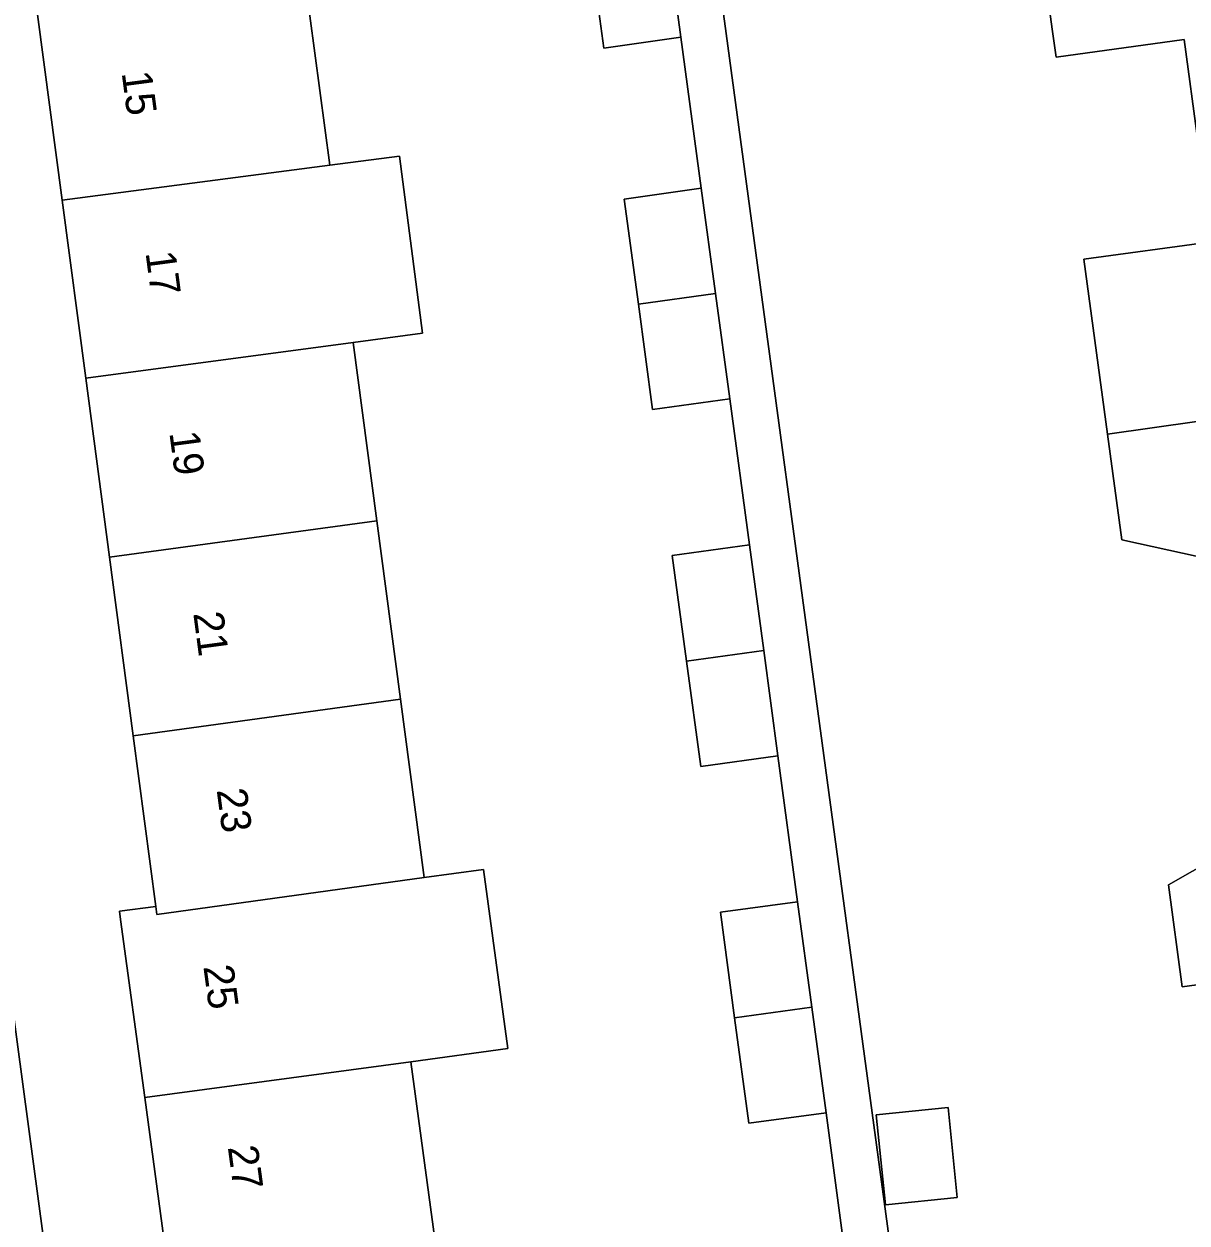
# Model space of a CAD drawing. Extents: x 163426 to 164192, y 380329 to 381641.
# Drawn here: x 163562.11 to 163600.88, y 381402.87 to 381442.84 of the extents above; entities that cross this region are included whole.
import ezdxf

# ---------------------------------------------------------------- set-up
doc = ezdxf.new("R2010")
doc.units = 0
for name, color, linetype in [('IMGEO_Erf', 7, 'Continuous'), ('IMGEO_Pand', 7, 'Continuous'), ('IMGEO_Pand_nummerreeks', 7, 'Continuous'), ('IMGEO_Voetpad_open', 7, 'Continuous')]:
    doc.layers.add(name, color=color, linetype=linetype)

msp = doc.modelspace()

# ---------------------------------------------------------------- linework, layer by layer
at = {"layer": 'IMGEO_Erf'}
for points in [[(163601.242, 381438.946), (163600.786, 381442.315), (163596.517, 381441.737), (163596.391, 381442.666), (163595.72, 381447.62)], [(163589.501, 381401.702), (163588.848, 381406.545), (163586.273, 381406.198), (163585.799, 381409.71), (163585.325, 381413.226), (163587.899, 381413.578), (163587.243, 381418.441), (163584.669, 381418.086), (163584.195, 381421.6), (163583.72, 381425.123), (163586.294, 381425.473), (163585.637, 381430.346), (163583.064, 381429.983), (163582.59, 381433.497), (163582.117, 381437.001), (163584.689, 381437.369), (163584.011, 381442.4), (163581.439, 381442.03), (163580.811, 381446.687)], [(163585.004, 381446.309), (163592.085, 381393.976)], [(163571.471, 381444.365), (163572.3, 381438.127), (163574.624, 381438.431), (163575.395, 381432.527), (163573.084, 381432.225), (163573.875, 381426.278), (163574.664, 381420.334), (163575.455, 381414.385), (163577.43, 381414.653), (163578.239, 381408.682), (163575.006, 381408.241), (163575.808, 381402.329)], [(163557.232, 381443.507), (163566.206, 381376.628), (163570.178, 381377.161), (163569.35, 381383.284), (163568.544, 381389.24), (163567.74, 381395.178), (163566.936, 381401.125), (163566.134, 381407.052), (163565.331, 381412.988), (163565.293, 381413.269), (163566.504, 381413.42), (163565.75, 381419.111), (163564.961, 381425.061), (163564.17, 381431.032), (163563.384, 381436.962), (163562.564, 381443.153)], [(163601.284, 381425.078), (163598.705, 381425.644), (163598.229, 381429.159), (163597.438, 381435.003), (163601.697, 381435.579)], [(163603.179, 381411.077), (163600.723, 381410.745), (163600.263, 381414.138), (163602.585, 381415.466)]]:
    msp.add_lwpolyline(points, dxfattribs=at)
msp.add_lwpolyline([(163590.524, 381406.471), (163592.916, 381406.715), (163593.222, 381403.715), (163590.83, 381403.471)], close=True, dxfattribs=at)
at = {"layer": 'IMGEO_Pand'}
for points in [[(163601.242, 381438.946), (163609.79, 381440.096), (163609.708, 381440.698), (163610.578, 381440.816), (163610.14, 381444.028), (163609.27, 381443.909), (163608.94, 381446.33), (163606.347, 381445.989), (163602.09, 381445.43), (163601.69, 381448.44), (163595.72, 381447.62), (163596.391, 381442.666), (163596.517, 381441.737), (163600.786, 381442.315)], [(163581.439, 381442.03), (163584.011, 381442.4), (163583.384, 381447.045), (163580.811, 381446.687)], [(163563.384, 381436.962), (163572.3, 381438.127), (163571.471, 381444.365), (163567.519, 381443.827), (163562.564, 381443.153)], [(163604.182, 381430.011), (163603.784, 381432.938), (163608.262, 381433.547), (163610.64, 381433.87), (163610.31, 381436.291), (163611.179, 381436.409), (163610.742, 381439.611), (163609.873, 381439.492), (163609.79, 381440.096), (163601.242, 381438.946), (163601.697, 381435.579), (163597.438, 381435.003), (163598.229, 381429.159)], [(163563.384, 381436.962), (163564.17, 381431.032), (163573.084, 381432.225), (163575.395, 381432.527), (163574.624, 381438.431), (163572.3, 381438.127)], [(163582.59, 381433.497), (163585.164, 381433.852), (163584.689, 381437.369), (163582.117, 381437.001)], [(163582.59, 381433.497), (163583.064, 381429.983), (163585.637, 381430.346), (163585.164, 381433.852)], [(163564.961, 381425.061), (163573.875, 381426.278), (163573.084, 381432.225), (163564.17, 381431.032)], [(163614.756, 381421.994), (163614.673, 381422.6), (163615.545, 381422.719), (163615.105, 381425.941), (163614.232, 381425.821), (163613.9, 381428.25), (163611.522, 381427.927), (163607.044, 381427.318), (163606.633, 381430.344), (163604.182, 381430.011), (163598.229, 381429.159), (163598.705, 381425.644), (163601.284, 381425.078), (163601.476, 381423.658), (163601.932, 381420.287), (163606.191, 381420.865)], [(163564.961, 381425.061), (163565.75, 381419.111), (163574.664, 381420.334), (163573.875, 381426.278)], [(163584.195, 381421.6), (163586.768, 381421.957), (163586.294, 381425.473), (163583.72, 381425.123)], [(163614.756, 381421.994), (163606.191, 381420.865), (163601.932, 381420.287), (163602.388, 381416.923), (163602.585, 381415.466), (163600.263, 381414.138), (163600.723, 381410.745), (163603.179, 381411.077), (163609.163, 381411.874), (163608.765, 381414.827), (163613.232, 381415.429), (163615.61, 381415.75), (163615.278, 381418.179), (163616.15, 381418.298), (163615.711, 381421.51), (163614.838, 381421.39)], [(163584.195, 381421.6), (163584.669, 381418.086), (163587.243, 381418.441), (163586.768, 381421.957)], [(163574.664, 381420.334), (163565.75, 381419.111), (163566.504, 381413.42), (163566.539, 381413.155), (163575.455, 381414.385)], [(163577.43, 381414.653), (163575.455, 381414.385), (163566.539, 381413.155), (163566.504, 381413.42), (163565.293, 381413.269), (163565.331, 381412.988), (163566.134, 381407.052), (163575.006, 381408.241), (163578.239, 381408.682)], [(163588.374, 381410.06), (163587.899, 381413.578), (163585.325, 381413.226), (163585.799, 381409.71)], [(163588.374, 381410.06), (163585.799, 381409.71), (163586.273, 381406.198), (163588.848, 381406.545)], [(163566.936, 381401.125), (163575.808, 381402.329), (163575.006, 381408.241), (163566.134, 381407.052)], [(163590.524, 381406.471), (163590.83, 381403.471), (163593.222, 381403.715), (163592.916, 381406.715)]]:
    msp.add_lwpolyline(points, close=True, dxfattribs=at)
at = {"layer": 'IMGEO_Voetpad_open'}
for points in [[(163571.177, 381345.417), (163569.239, 381353.811), (163569.01, 381355.444), (163568.044, 381362.93), (163566.405, 381375.146), (163566.206, 381376.628), (163557.232, 381443.507), (163556.995, 381445.271), (163550.532, 381493.434), (163549.67, 381494.227), (163548.887, 381500), (163545.916, 381521.903)], [(163583.384, 381447.045), (163584.011, 381442.4), (163584.689, 381437.369), (163585.164, 381433.852), (163585.637, 381430.346), (163586.294, 381425.473), (163586.768, 381421.957), (163587.243, 381418.441), (163587.899, 381413.578), (163588.374, 381410.06), (163588.848, 381406.545), (163589.501, 381401.702)], [(163592.085, 381393.976), (163585.004, 381446.309)]]:
    msp.add_lwpolyline(points, dxfattribs=at)

# ---------------------------------------------------------------- texts
at = {"layer": 'IMGEO_Pand_nummerreeks'}
for s, rotation, p in [('15', 277.5484, (163565.363, 381441.213)), ('17', 277.5484, (163566.158, 381435.214)), ('19', 277.5484, (163566.953, 381429.214)), ('21', 277.5484, (163567.751, 381423.193)), ('23', 277.5456, (163568.531, 381417.305)), ('25', 277.7061, (163568.087, 381411.417)), ('27', 277.7047, (163568.901, 381405.399))]:
    msp.add_text(s, height=1, rotation=rotation, dxfattribs=at).set_placement(p)

doc.saveas('drawing.dxf')
